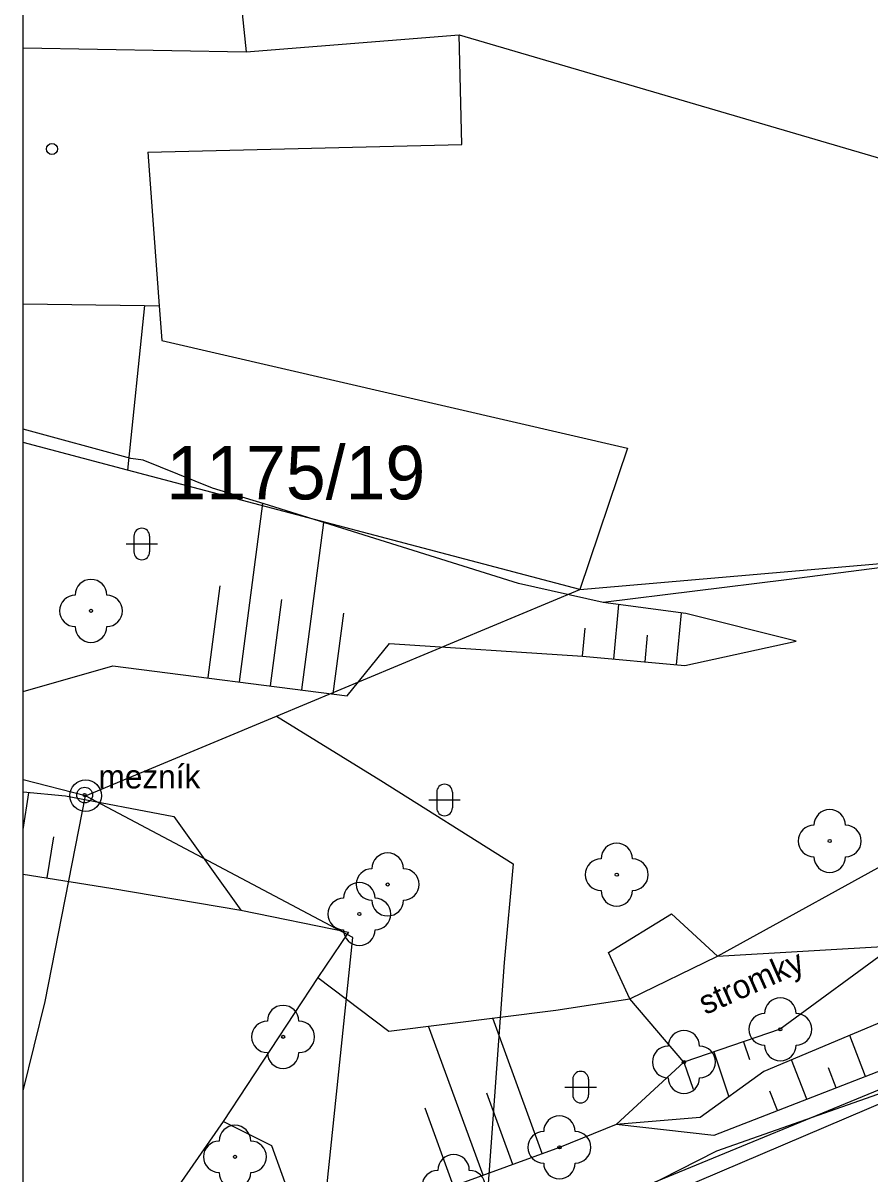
# Model space of a CAD drawing. Extents: x -564037 to -563722, y -1163561 to -1163412.
# Drawn here: x -564036.51 to -564009.62, y -1163511.24 to -1163474.68 of the extents above; entities that cross this region are included whole.
import ezdxf

# ---------------------------------------------------------------- set-up
doc = ezdxf.new("R2010")
doc.units = 0
for name, color, linetype in [('1', 7, 'Continuous'), ('Definiční bod kú', 7, 'Continuous'), ('Hranice parcel', 7, 'Continuous'), ('Parcelní čísla', 7, 'Continuous'), ('Vnitřní kresba', 7, 'Continuous'), ('Vrstva 14', 7, 'Continuous'), ('Vrstva 21', 7, 'Continuous'), ('Vrstva 22', 7, 'Continuous'), ('Vrstva 24', 7, 'Continuous'), ('Vrstva 25', 7, 'Continuous'), ('Vrstva 41', 7, 'Continuous'), ('Vrstva 48', 7, 'Continuous'), ('Značky bodu BP', 7, 'Continuous'), ('Značky budov', 7, 'Continuous')]:
    doc.layers.add(name, color=color, linetype=linetype)

msp = doc.modelspace()

# ---------------------------------------------------------------- linework, layer by layer
msp.add_lwpolyline([(-563982.839, -1163488.47), (-563983.409, -1163491.846), (-563990.891, -1163500.051), (-563993.495, -1163501.54), (-564001.695, -1163505.76), (-564021.072, -1163514.028), (-564021.939, -1163519.359), (-564028.021, -1163535.92), (-563982.332, -1163543.556), (-563870.708, -1163549.442), (-563829.278, -1163493.346), (-563857.264, -1163473.56), (-563873.956, -1163464.96), (-563885.354, -1163462.845), (-563964.187, -1163417.135), (-563977.612, -1163460.096), (-563977.509, -1163470.055), (-563981.031, -1163479.642), (-563982.839, -1163488.47)])
at = {"layer": '1'}
msp.add_lwpolyline([(-564036.505, -1163412.494), (-563721.505, -1163412.494), (-563721.505, -1163560.994), (-564036.505, -1163560.994)], close=True, dxfattribs=at)
at = {"layer": 'Definiční bod kú'}
msp.add_lwpolyline([(-564036.505, -1163529.976), (-564035.88, -1163528.59), (-564032.62, -1163523.46), (-564027.5, -1163518.53), (-564023.88, -1163515.79), (-564019.18, -1163512.89), (-564014.48, -1163510.5), (-564004.65, -1163507.04), (-563996.46, -1163502.51), (-563993.72, -1163500.97), (-563990.58, -1163498.69), (-563987.18, -1163495.32), (-563983.19, -1163487.81), (-563979.82, -1163480.39), (-563975.55, -1163472.37), (-563971.76, -1163466.68), (-563970.57, -1163458.32), (-563969.42, -1163449.87), (-563967.93, -1163441.99), (-563966.12, -1163434.66), (-563963.95, -1163427.04), (-563963.19, -1163422.98), (-563961.48, -1163418.93), (-563957.126, -1163412.494)], dxfattribs=at)
at = {"layer": 'Hranice parcel'}
for p, q in [((-564032.65, -1163483.65), (-564033.19, -1163488.88)), ((-564033.19, -1163488.88), (-564036.505, -1163488.003)), ((-564018.83, -1163492.67), (-564033.19, -1163488.88)), ((-564018.83, -1163492.67), (-564003.59, -1163491.36)), ((-564028.46, -1163496.69), (-564018.83, -1163492.67)), ((-564034.52, -1163499.22), (-564028.46, -1163496.69))]:
    msp.add_line(p, q, dxfattribs=at)
for points in [[(-563978.16, -1163460.35), (-563977.81, -1163470.18), (-563986.9, -1163494.46), (-563994.41, -1163501.54), (-564003.29, -1163506.07), (-564021.9, -1163513.74)], [(-564036.505, -1163475.472), (-564029.42, -1163475.59), (-564022.66, -1163475.05), (-564001.49, -1163481.27)], [(-564036.505, -1163483.596), (-564032.65, -1163483.65)], [(-564032.65, -1163483.65), (-564032.18, -1163483.66), (-564032.1, -1163484.76), (-564017.32, -1163488.18), (-564018.83, -1163492.67)], [(-564028.46, -1163496.69), (-564025.15, -1163498.74), (-564020.95, -1163501.38), (-564021.23, -1163504.52), (-564021.9, -1163513.74)], [(-564034.52, -1163499.22), (-564036.505, -1163498.716)], [(-564036.505, -1163508.595), (-564035.8, -1163505.76), (-564034.52, -1163499.22)], [(-564033.84, -1163535.6), (-564027.54, -1163518.14), (-564026.04, -1163503.72), (-564034.52, -1163499.22)]]:
    msp.add_lwpolyline(points, dxfattribs=at)
at = {"layer": 'Vnitřní kresba'}
for p, q in [((-564030.92, -1163461.24), (-564029.42, -1163475.59)), ((-564022.58, -1163478.54), (-564022.66, -1163475.05)), ((-564032.54, -1163478.78), (-564022.58, -1163478.54)), ((-564032.54, -1163478.78), (-564032.18, -1163483.66))]:
    msp.add_line(p, q, dxfattribs=at)
at = {"layer": 'Vrstva 14'}
for points in [[(-563978.09, -1163460.32), (-563977.36, -1163462.71), (-563977.84, -1163465.15), (-563976.09, -1163465.55), (-563974.34, -1163466.75), (-563974.1, -1163467.69), (-563974.4, -1163469.44), (-563976.73, -1163469.93), (-563977.88, -1163469.51), (-563978.75, -1163470.09), (-563979.22, -1163471.2), (-563981.47, -1163479.57), (-563983.82, -1163487.72), (-563987.7, -1163494.99), (-563990.79, -1163498.34), (-563994.06, -1163500.55), (-563996.65, -1163502.12), (-564005.13, -1163506.34), (-564014.58, -1163510.01)], [(-564033.08, -1163488.51), (-564036.505, -1163487.58)], [(-564032.69, -1163488.56), (-564033.08, -1163488.51)], [(-564005.7, -1163491.6), (-564006.2, -1163491.58), (-564012.27, -1163492.36), (-564018.09, -1163493.08), (-564020.78, -1163492.48), (-564028.85, -1163489.95), (-564030.49, -1163489.45), (-564032.69, -1163488.56)], [(-564027.15, -1163505), (-564024.9, -1163506.7), (-564019.59, -1163506.03), (-564017.25, -1163505.67), (-564014.46, -1163504.32), (-564008.13, -1163500.82), (-564005.74, -1163499.66), (-563997.05, -1163495.87), (-563995.48, -1163492.66)], [(-564011.97, -1163494.31), (-564015.47, -1163493.43), (-564018.09, -1163493.08)], [(-564036.505, -1163495.911), (-564033.65, -1163495.1), (-564026.22, -1163496.05), (-564024.87, -1163494.39), (-564018.75, -1163494.79), (-564015.5, -1163495.09), (-564011.97, -1163494.31)], [(-563991.13, -1163497.04), (-563995.37, -1163499.78), (-563998.83, -1163501.38), (-564002.12, -1163503), (-564008.59, -1163506.13), (-564012.99, -1163507.98), (-564015.01, -1163509.44), (-564017.68, -1163509.66)], [(-564036.505, -1163499.099), (-564035.16, -1163499.22), (-564031.72, -1163499.88), (-564029.59, -1163502.86)], [(-564036.505, -1163501.708), (-564033.72, -1163502.16), (-564029.59, -1163502.86), (-564026.18, -1163503.55), (-564027.15, -1163505), (-564030.15, -1163509.57), (-564034.03, -1163515.15), (-564036.505, -1163518.922)], [(-564008.87, -1163503.99), (-564012.47, -1163506.64), (-564015.53, -1163507.68), (-564017.68, -1163509.66), (-564019.48, -1163510.39), (-564022.84, -1163511.62), (-564024.26, -1163512.8), (-564027.09, -1163514.75), (-564027.62, -1163513.07), (-564028.61, -1163510.34), (-564030.15, -1163509.57)], [(-564014.58, -1163510.01), (-564017.68, -1163509.66)]]:
    msp.add_lwpolyline(points, dxfattribs=at)
at = {"layer": 'Vrstva 21'}
for points in [[(-564017.25, -1163505.67), (-564017.92, -1163504.2), (-564015.92, -1163502.97), (-564014.46, -1163504.32)], [(-564014.46, -1163504.32), (-564008.87, -1163503.99)], [(-564015.53, -1163507.68), (-564017.25, -1163505.67)]]:
    msp.add_lwpolyline(points, dxfattribs=at)
at = {"layer": 'Vrstva 22'}
for centre in [(-564034.35, -1163493.35), (-564010.9, -1163500.66), (-564017.66, -1163501.73), (-564024.93, -1163502.04), (-564025.83, -1163502.98), (-564012.47, -1163506.64), (-564028.25, -1163506.88), (-564015.53, -1163507.68), (-564019.48, -1163510.39), (-564029.78, -1163510.69)]:
    msp.add_circle(centre, 0.05, dxfattribs=at)
for centre, start, end in [((-564034.35, -1163492.85), 0, 180), ((-564034.85, -1163493.35), 90, 270), ((-564033.85, -1163493.35), 270, 90), ((-564034.35, -1163493.85), 180, 0), ((-564010.9, -1163500.16), 0, 180), ((-564011.4, -1163500.66), 90, 270), ((-564010.4, -1163500.66), 270, 90), ((-564017.66, -1163501.23), 0, 180), ((-564024.93, -1163501.54), 0, 180), ((-564010.9, -1163501.16), 180, 0), ((-564025.43, -1163502.04), 90, 270), ((-564024.43, -1163502.04), 270, 90), ((-564018.16, -1163501.73), 90, 270), ((-564017.16, -1163501.73), 270, 90), ((-564025.83, -1163502.48), 0, 180), ((-564017.66, -1163502.23), 180, 0), ((-564026.33, -1163502.98), 90, 270), ((-564024.93, -1163502.54), 180, 0), ((-564025.33, -1163502.98), 270, 90), ((-564025.83, -1163503.48), 180, 0), ((-564028.25, -1163506.38), 0, 180), ((-564012.47, -1163506.14), 0, 180), ((-564012.97, -1163506.64), 90, 270), ((-564011.97, -1163506.64), 270, 90), ((-564028.75, -1163506.88), 90, 270), ((-564027.75, -1163506.88), 270, 90), ((-564015.53, -1163507.18), 0, 180), ((-564028.25, -1163507.38), 180, 0), ((-564016.03, -1163507.68), 90, 270), ((-564015.03, -1163507.68), 270, 90), ((-564012.47, -1163507.14), 180, 0), ((-564015.53, -1163508.18), 180, 0), ((-564019.48, -1163509.89), 0, 180), ((-564029.78, -1163510.19), 0, 180), ((-564019.98, -1163510.39), 90, 270), ((-564018.98, -1163510.39), 270, 90), ((-564030.28, -1163510.69), 90, 270), ((-564029.28, -1163510.69), 270, 90), ((-564022.84, -1163511.12), 0, 180), ((-564019.48, -1163510.89), 180, 0), ((-564029.78, -1163511.19), 180, 0), ((-564023.34, -1163511.62), 90, 270), ((-564022.34, -1163511.62), 270, 90)]:
    msp.add_arc(centre, 0.5, start, end, dxfattribs=at)
at = {"layer": 'Vrstva 24'}
for radius in [0.25, 0.05]:
    msp.add_circle((-564034.55, -1163499.2), radius, dxfattribs=at)
at = {"layer": 'Vrstva 25'}
for p, q in [((-564032.986, -1163490.976), (-564032.986, -1163491.476)), ((-564032.486, -1163490.976), (-564032.486, -1163491.476)), ((-564033.236, -1163491.226), (-564032.236, -1163491.226)), ((-564023.626, -1163499.356), (-564022.626, -1163499.356)), ((-564023.376, -1163499.106), (-564023.376, -1163499.606)), ((-564022.876, -1163499.106), (-564022.876, -1163499.606)), ((-564019.306, -1163508.476), (-564018.306, -1163508.476)), ((-564019.056, -1163508.226), (-564019.056, -1163508.726)), ((-564018.556, -1163508.226), (-564018.556, -1163508.726))]:
    msp.add_line(p, q, dxfattribs=at)
for centre, start, end in [((-564032.736, -1163490.976), 0, 180), ((-564032.736, -1163491.476), 180, 0), ((-564023.126, -1163499.106), 0, 180), ((-564023.126, -1163499.606), 180, 0), ((-564018.806, -1163508.226), 0, 180), ((-564018.806, -1163508.726), 180, 0)]:
    msp.add_arc(centre, 0.25, start, end, dxfattribs=at)
at = {"layer": 'Vrstva 48'}
for p, q in [((-564029.638, -1163495.6), (-564028.895, -1163489.936)), ((-564027.655, -1163495.86), (-564026.958, -1163490.546)), ((-564030.63, -1163495.47), (-564030.247, -1163492.55)), ((-564028.647, -1163495.73), (-564028.287, -1163492.986)), ((-564017.754, -1163494.882), (-564017.594, -1163493.146)), ((-564026.664, -1163495.99), (-564026.327, -1163493.421)), ((-564015.763, -1163495.066), (-564015.61, -1163493.411)), ((-564018.75, -1163494.79), (-564018.668, -1163493.902)), ((-564016.758, -1163494.974), (-564016.68, -1163494.126)), ((-564036.505, -1163500.289), (-564036.318, -1163499.128)), ((-564035.741, -1163501.829), (-564035.531, -1163500.525)), ((-564020.023, -1163510.589), (-564021.599, -1163506.283)), ((-564021.901, -1163511.276), (-564023.635, -1163506.54)), ((-564013.637, -1163507.034), (-564013.444, -1163507.601)), ((-564009.762, -1163508.137), (-564010.266, -1163506.835)), ((-564014.584, -1163507.357), (-564014.098, -1163508.781)), ((-564015.53, -1163507.68), (-564015.238, -1163508.537)), ((-564011.627, -1163508.859), (-564012.111, -1163507.61)), ((-564010.695, -1163508.498), (-564010.942, -1163507.86)), ((-564020.962, -1163510.932), (-564021.789, -1163508.672)), ((-564012.56, -1163509.22), (-564012.797, -1163508.609)), ((-564022.84, -1163511.62), (-564023.746, -1163509.144))]:
    msp.add_line(p, q, dxfattribs=at)
at = {"layer": 'Značky bodu BP'}
for radius in [0.5, 0.0303]:
    msp.add_circle((-564034.52, -1163499.22), radius, dxfattribs=at)
at = {"layer": 'Značky budov'}
msp.add_circle((-564035.587, -1163478.679), 0.175, dxfattribs=at)

# ---------------------------------------------------------------- texts
at = {"layer": 'Parcelní čísla'}
msp.add_text('1175/19', height=1.7, dxfattribs=at).set_placement((-564031.956, -1163489.81))
at = {"layer": 'Vrstva 41'}
msp.add_text('mezník', height=0.75, dxfattribs=at).set_placement((-564034.11, -1163498.99))
msp.add_text('stromky', height=0.75, rotation=23.9211, dxfattribs=at).set_placement((-564014.85, -1163506.19))

doc.saveas('drawing.dxf')
